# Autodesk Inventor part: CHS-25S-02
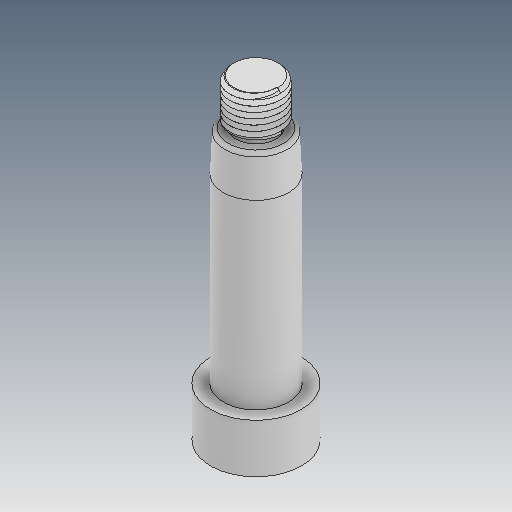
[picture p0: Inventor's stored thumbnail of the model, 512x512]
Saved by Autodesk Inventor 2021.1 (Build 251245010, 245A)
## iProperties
Created: 2021-05
Part Number: CHS-25S-02
Material: Ogólny
Document SubType Name: Modeling
Designer: user
Density: 1 g/cm^3
Appearance: Domyślna
Author: user
Revision Number: ÈÎºÎ
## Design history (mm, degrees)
feature "ÊäÈë1"
feature "ÊäÈë2"
node "Bryła1"
node "Bryła2"
